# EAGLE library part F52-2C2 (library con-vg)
CONNECTOR female, 52 pins + 2 coax, type C
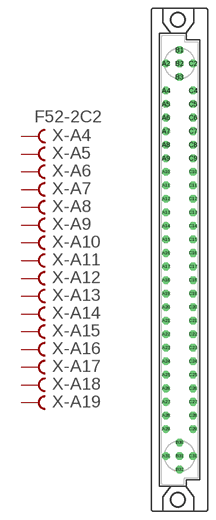
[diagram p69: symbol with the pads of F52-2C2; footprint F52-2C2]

Designator prefix X; gates -A4=FVAL -A5=FEM -A6=FEM -A7=FEM -A8=FEM -A9=FEM -A10=FEM -A11=FEM -A12=FEM -A13=FEM -A14=FEM -A15=FEM -A16=FEM -A17=FEM -A18=FEM -A19=FEM -A20=FEM -A21=FEM -A22=FEM -A23=FEM -A24=FEM -A25=FEM -A26=FEM -A27=FEM -A28=FEM -A29=FEM -C4=FVAL -C5=FEM -C6=FEM -C7=FEM -C8=FEM -C9=FEM -C10=FEM -C11=FEM -C12=FEM -C13=FEM -C14=FEM -C15=FEM -C16=FEM -C17=FEM -C18=FEM -C19=FEM -C20=FEM -C21=FEM -C22=FEM -C23=FEM -C24=FEM -C25=FEM -C26=FEM -C27=FEM -C28=FEM -C29=FEM -1=COAX -2=COAX

## F52-2C2  [F52-2C2]
A2  -1:S3  pas
A4  -A4:B  pas
A5  -A5:B  pas
A6  -A6:B  pas
A7  -A7:B  pas
A8  -A8:B  pas
A9  -A9:B  pas
A10  -A10:B  pas
A11  -A11:B  pas
A12  -A12:B  pas
A13  -A13:B  pas
A14  -A14:B  pas
A15  -A15:B  pas
A16  -A16:B  pas
A17  -A17:B  pas
A18  -A18:B  pas
A19  -A19:B  pas
A20  -A20:B  pas
A21  -A21:B  pas
A22  -A22:B  pas
A23  -A23:B  pas
A24  -A24:B  pas
A25  -A25:B  pas
A26  -A26:B  pas
A27  -A27:B  pas
A28  -A28:B  pas
A29  -A29:B  pas
A31  -2:S3  pas
B1  -1:S1  pas
B2  -1:S  pas
B3  -1:S2  pas
B30  -2:S1  pas
B31  -2:S  pas
B32  -2:S2  pas
C2  -1:S4  pas
C4  -C4:B  pas
C5  -C5:B  pas
C6  -C6:B  pas
C7  -C7:B  pas
C8  -C8:B  pas
C9  -C9:B  pas
C10  -C10:B  pas
C11  -C11:B  pas
C12  -C12:B  pas
C13  -C13:B  pas
C14  -C14:B  pas
C15  -C15:B  pas
C16  -C16:B  pas
C17  -C17:B  pas
C18  -C18:B  pas
C19  -C19:B  pas
C20  -C20:B  pas
C21  -C21:B  pas
C22  -C22:B  pas
C23  -C23:B  pas
C24  -C24:B  pas
C25  -C25:B  pas
C26  -C26:B  pas
C27  -C27:B  pas
C28  -C28:B  pas
C29  -C29:B  pas
C31  -2:S4  pas

## Footprint F52-2C2 (pad centres in mm)
CONNECTOR female, 52 pins + 2 coax, type C
drill 0.914 octagon: A2 -2.54,36.83; A4 -2.54,31.75; A5 -2.54,29.21; A6 -2.54,26.67; A7 -2.54,24.13; A8 -2.54,21.59; A9 -2.54,19.05; A10 -2.54,16.51; A11 -2.54,13.97; A12 -2.54,11.43; A13 -2.54,8.89; A14 -2.54,6.35; A15 -2.54,3.81; A16 -2.54,1.27; A17 -2.54,-1.27; A18 -2.54,-3.81; A19 -2.54,-6.35; A20 -2.54,-8.89; A21 -2.54,-11.43; A22 -2.54,-13.97; A23 -2.54,-16.51; A24 -2.54,-19.05; A25 -2.54,-21.59; A26 -2.54,-24.13; A27 -2.54,-26.67; A28 -2.54,-29.21; A29 -2.54,-31.75; A31 -2.54,-36.83; B1 0,39.37; B2 0,36.83; B3 0,34.29; B30 0,-34.29; B31 0,-36.83; B32 0,-39.37; C2 2.54,36.83; C4 2.54,31.75; C5 2.54,29.21; C6 2.54,26.67; C7 2.54,24.13; C8 2.54,21.59; C9 2.54,19.05; C10 2.54,16.51; C11 2.54,13.97; C12 2.54,11.43; C13 2.54,8.89; C14 2.54,6.35; C15 2.54,3.81; C16 2.54,1.27; C17 2.54,-1.27; C18 2.54,-3.81; C19 2.54,-6.35; C20 2.54,-8.89; C21 2.54,-11.43; C22 2.54,-13.97; C23 2.54,-16.51; C24 2.54,-19.05; C25 2.54,-21.59; C26 2.54,-24.13; C27 2.54,-26.67; C28 2.54,-29.21; C29 2.54,-31.75; C31 2.54,-36.83
hole 2.794 at -0.305,45.009
hole 2.794 at -0.305,-45.009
